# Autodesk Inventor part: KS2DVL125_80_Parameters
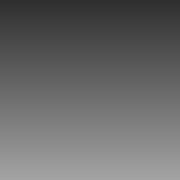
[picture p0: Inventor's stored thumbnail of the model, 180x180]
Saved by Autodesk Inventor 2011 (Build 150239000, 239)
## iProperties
Created: 2010-11
Document SubType Name: Modeling
Designer: TB
Density: 1 g/cm^3
Slaglengde: 100,000 mm
Vinkel_Minusport: 0.00 deg
Forlengelse_rør: 0.000 mm
Minusport2: 180.00 deg
Author: TB
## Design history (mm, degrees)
other parameters: "Slaglengde" = 100 [user parameter], "Forlengelse_rør" = 0 [user parameter], "Vinkel_Minusport" = 0 deg [user parameter], "Minusport2" = 180 deg [user parameter]
